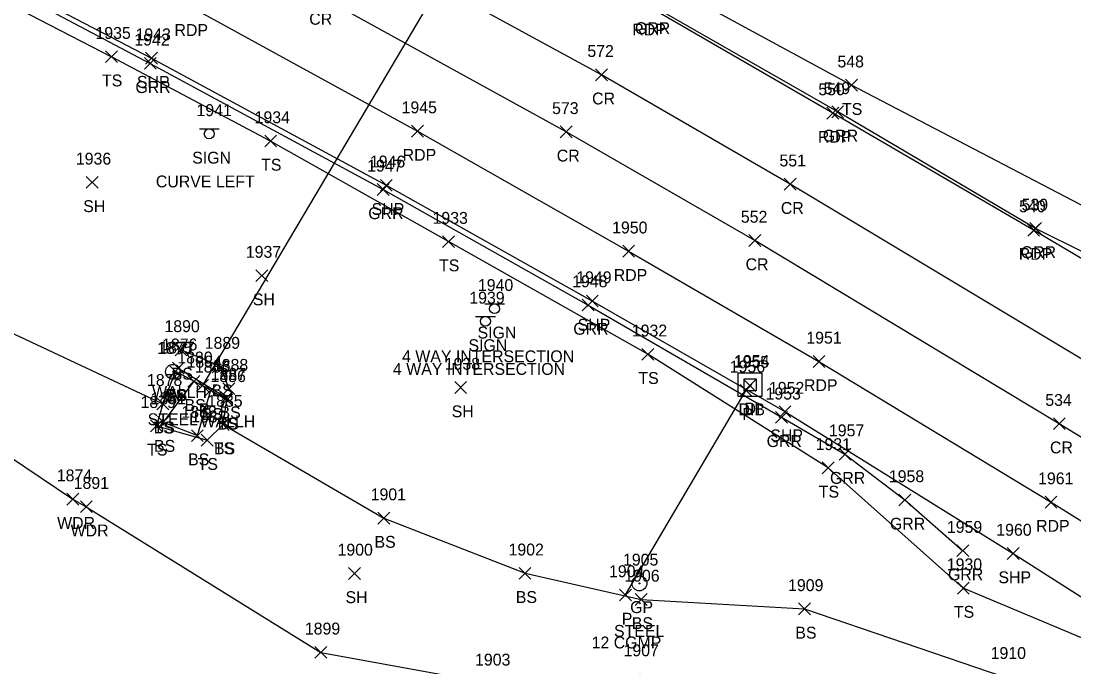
# Model space of a CAD drawing. Extents: x 1629176 to 1637209, y 606063 to 610167.
# Drawn here: x 1630435.7 to 1630613, y 606610.8 to 606719.6 of the extents above; entities that cross this region are included whole.
import ezdxf

# ---------------------------------------------------------------- set-up
doc = ezdxf.new("R2010")
doc.units = 0
for name, color, linetype in [('D_A', 7, 'Continuous'), ('D_C', 7, 'Continuous'), ('D_I', 7, 'Continuous'), ('D_TIC', 7, 'Continuous'), ('DCP', 7, 'Continuous'), ('DHW', 7, 'Continuous'), ('DS', 7, 'Continuous'), ('L_A', 7, 'Continuous'), ('L_I', 7, 'Continuous'), ('L_TIC', 7, 'Continuous'), ('LAWA', 7, 'Continuous'), ('LELB', 7, 'Continuous'), ('P_A', 7, 'Continuous'), ('P_I', 7, 'Continuous'), ('P_TIC', 7, 'Continuous'), ('PET', 7, 'Continuous'), ('PRC', 7, 'Continuous'), ('PSP', 7, 'Continuous'), ('R_A', 7, 'Continuous'), ('R_C', 7, 'Continuous'), ('R_I', 7, 'Continuous'), ('R_TIC', 7, 'Continuous'), ('RGP', 7, 'Continuous'), ('RGR', 7, 'Continuous'), ('S_A', 7, 'Continuous'), ('S_C', 7, 'Continuous'), ('S_I', 7, 'Continuous'), ('SSGN', 7, 'Continuous')]:
    doc.layers.add(name, color=color, linetype=linetype)

msp = doc.modelspace()

# ---------------------------------------------------------------- linework, layer by layer
at = {"layer": 'D_TIC'}
for points in [[(1630461.15, 606660.13), (1630463.15, 606662.13)], [(1630463.15, 606660.13), (1630461.15, 606662.13)], [(1630465.23, 606657.23), (1630467.23, 606659.23)], [(1630467.23, 606657.23), (1630465.23, 606659.23)], [(1630557.38, 606657.21), (1630559.38, 606659.21)], [(1630559.38, 606657.21), (1630557.38, 606659.21)], [(1630469.3, 606655.17), (1630471.3, 606657.17)], [(1630471.3, 606655.17), (1630469.3, 606657.17)], [(1630556.75, 606656.41), (1630558.75, 606658.41)], [(1630558.75, 606656.41), (1630556.75, 606658.41)], [(1630536.46, 606621.94), (1630538.46, 606623.94)], [(1630538.46, 606621.94), (1630536.46, 606623.94)]]:
    msp.add_lwpolyline(points, dxfattribs=at)
at = {"layer": 'DCP'}
for points in [[(1630562.44, 606820.77), (1630466.23, 606658.23)], [(1630537.46, 606622.94), (1630557.75, 606657.41)]]:
    msp.add_lwpolyline(points, dxfattribs=at)
at = {"layer": 'DHW'}
msp.add_lwpolyline([(1630462.15, 606661.13), (1630470.3, 606656.17)], dxfattribs=at)
at = {"layer": 'DS'}
for p, q in [((1630556.43, 606660.35), (1630560.43, 606660.35)), ((1630556.43, 606656.35), (1630556.43, 606660.35)), ((1630557.43, 606657.35), (1630557.43, 606659.35)), ((1630557.43, 606659.35), (1630559.43, 606659.35)), ((1630559.43, 606659.35), (1630559.43, 606657.35)), ((1630560.43, 606660.35), (1630560.43, 606656.35)), ((1630559.43, 606657.35), (1630557.43, 606657.35)), ((1630558.44, 606658.35), (1630558.44, 606658.35)), ((1630558.44, 606658.35), (1630558.44, 606658.35)), ((1630560.43, 606656.35), (1630556.43, 606656.35))]:
    msp.add_line(p, q, dxfattribs=at)
at = {"layer": 'L_TIC'}
for points in [[(1630449.89, 606712.6), (1630451.89, 606714.6)], [(1630451.89, 606712.6), (1630449.89, 606714.6)], [(1630449.89, 606712.6), (1630451.89, 606714.6)], [(1630451.89, 606712.6), (1630449.89, 606714.6)], [(1630574.5, 606707.79), (1630576.5, 606709.79)], [(1630576.5, 606707.79), (1630574.5, 606709.79)], [(1630476.7, 606698.4), (1630478.7, 606700.4)], [(1630478.7, 606698.4), (1630476.7, 606700.4)], [(1630446.65, 606691.43), (1630448.65, 606693.43)], [(1630448.65, 606691.43), (1630446.65, 606693.43)], [(1630506.65, 606681.45), (1630508.65, 606683.45)], [(1630508.65, 606681.45), (1630506.65, 606683.45)], [(1630475.21, 606675.73), (1630477.21, 606677.73)], [(1630477.21, 606675.73), (1630475.21, 606677.73)], [(1630461.6, 606663.21), (1630463.6, 606665.21)], [(1630463.6, 606663.21), (1630461.6, 606665.21)], [(1630540.22, 606662.48), (1630542.22, 606664.48)], [(1630542.22, 606662.48), (1630540.22, 606664.48)], [(1630460.65, 606659.61), (1630462.65, 606661.61)], [(1630462.65, 606659.61), (1630460.65, 606661.61)], [(1630460.65, 606659.61), (1630462.65, 606661.61)], [(1630462.65, 606659.61), (1630460.65, 606661.61)], [(1630468.3, 606660.4), (1630470.3, 606662.4)], [(1630470.3, 606660.4), (1630468.3, 606662.4)], [(1630463.76, 606657.93), (1630465.76, 606659.93)], [(1630465.76, 606657.93), (1630463.76, 606659.93)], [(1630463.76, 606657.93), (1630465.76, 606659.93)], [(1630465.76, 606657.93), (1630463.76, 606659.93)], [(1630466.64, 606656.41), (1630468.64, 606658.41)], [(1630468.64, 606656.41), (1630466.64, 606658.41)], [(1630466.64, 606656.41), (1630468.64, 606658.41)], [(1630468.64, 606656.41), (1630466.64, 606658.41)], [(1630469.66, 606656.69), (1630471.66, 606658.69)], [(1630471.66, 606656.69), (1630469.66, 606658.69)], [(1630508.7, 606656.87), (1630510.7, 606658.87)], [(1630510.7, 606656.87), (1630508.7, 606658.87)], [(1630458.56, 606654.15), (1630460.56, 606656.15)], [(1630460.56, 606654.15), (1630458.56, 606656.15)], [(1630458.56, 606654.15), (1630460.56, 606656.15)], [(1630460.56, 606654.15), (1630458.56, 606656.15)], [(1630469.33, 606654.8), (1630471.33, 606656.8)], [(1630471.33, 606654.8), (1630469.33, 606656.8)], [(1630469.33, 606654.8), (1630471.33, 606656.8)], [(1630471.33, 606654.8), (1630469.33, 606656.8)], [(1630457.49, 606650.43), (1630459.49, 606652.43)], [(1630459.49, 606650.43), (1630457.49, 606652.43)], [(1630458.62, 606651.05), (1630460.62, 606653.05)], [(1630460.62, 606651.05), (1630458.62, 606653.05)], [(1630468.72, 606650.64), (1630470.72, 606652.64)], [(1630470.72, 606650.64), (1630468.72, 606652.64)], [(1630468.72, 606650.64), (1630470.72, 606652.64)], [(1630470.72, 606650.64), (1630468.72, 606652.64)], [(1630464.36, 606648.78), (1630466.36, 606650.78)], [(1630466.36, 606648.78), (1630464.36, 606650.78)], [(1630466, 606648), (1630468, 606650)], [(1630468, 606648), (1630466, 606650)], [(1630570.59, 606643.34), (1630572.59, 606645.34)], [(1630572.59, 606643.34), (1630570.59, 606645.34)], [(1630443.38, 606638.08), (1630445.38, 606640.08)], [(1630445.38, 606638.08), (1630443.38, 606640.08)], [(1630445.66, 606636.81), (1630447.66, 606638.81)], [(1630447.66, 606636.81), (1630445.66, 606638.81)], [(1630495.75, 606634.89), (1630497.75, 606636.89)], [(1630497.75, 606634.89), (1630495.75, 606636.89)], [(1630490.82, 606625.57), (1630492.82, 606627.57)], [(1630492.82, 606625.57), (1630490.82, 606627.57)], [(1630519.54, 606625.59), (1630521.54, 606627.59)], [(1630521.54, 606625.59), (1630519.54, 606627.59)], [(1630593.34, 606623.1), (1630595.34, 606625.1)], [(1630595.34, 606623.1), (1630593.34, 606625.1)], [(1630539.08, 606621.19), (1630541.08, 606623.19)], [(1630541.08, 606621.19), (1630539.08, 606623.19)], [(1630566.61, 606619.59), (1630568.61, 606621.59)], [(1630568.61, 606619.59), (1630566.61, 606621.59)], [(1630485.16, 606612.28), (1630487.16, 606614.28)], [(1630487.16, 606612.28), (1630485.16, 606614.28)]]:
    msp.add_lwpolyline(points, dxfattribs=at)
at = {"layer": 'LAWA'}
msp.add_lwpolyline([(1630297.68, 606682.91), (1630335.71, 606675.48), (1630386.4, 606666.36), (1630422.65, 606653.68), (1630444.38, 606639.08), (1630446.66, 606637.81), (1630486.16, 606613.28), (1630514.89, 606608.05), (1630539.89, 606609.62), (1630562.09, 606603.08), (1630591.48, 606594.03), (1630626, 606578), (1630626.04, 606578.1), (1630670.33, 606553.73), (1630697.07, 606528.38), (1630722.88, 606501.58)], dxfattribs=at)
at = {"layer": 'LELB'}
for points in [[(1630772.3, 606583.26), (1630744.36, 606600.82), (1630702.09, 606628.01), (1630669.73, 606653.69), (1630639.16, 606677.6), (1630625.62, 606682.65), (1630575.5, 606708.79), (1630543.73, 606726.11), (1630517.88, 606742.14), (1630478.23, 606762.96), (1630430.43, 606788.65), (1630392.8, 606806.98), (1630357.66, 606823.31), (1630317.9, 606842.29), (1630273.51, 606862.27), (1630239.69, 606876.29), (1630209.67, 606888.82), (1630166.54, 606905.65), (1630125.1, 606921.22), (1630084.2, 606935.53), (1630049.16, 606947.36)], [(1630044.25, 606889.35), (1630091.41, 606872.59), (1630136.9, 606855.8), (1630181.87, 606838.43), (1630229.1, 606819.13), (1630265.76, 606803.15), (1630304.81, 606785.31), (1630348.18, 606765.13), (1630385.69, 606747.11), (1630426.71, 606726.12), (1630450.89, 606713.6)], [(1630053.59, 606794.16), (1630081.62, 606779.15), (1630106.52, 606768.08), (1630137.48, 606760.05), (1630167.15, 606751.57), (1630192.23, 606740.71), (1630218.23, 606736.11), (1630252.15, 606733.42), (1630290.4, 606729.57), (1630313.6, 606719.08), (1630348.91, 606706.34), (1630395.46, 606688.14), (1630428.07, 606669.89), (1630459.56, 606655.15)], [(1630743.82, 606536.58), (1630708.63, 606560.3), (1630674.18, 606582.22), (1630637.64, 606605.88), (1630594.34, 606624.1), (1630571.59, 606644.34), (1630541.22, 606663.48), (1630507.65, 606682.45), (1630477.7, 606699.4), (1630450.89, 606713.6)], [(1630470.66, 606657.69), (1630469.3, 606661.4), (1630462.6, 606664.21)], [(1630461.65, 606660.61), (1630459.56, 606655.15), (1630458.49, 606651.43), (1630467, 606649), (1630469.72, 606651.64), (1630470.33, 606655.8)], [(1630461.65, 606660.61), (1630464.76, 606658.93), (1630467.64, 606657.41), (1630470.33, 606655.8)], [(1630464.76, 606658.93), (1630459.62, 606652.05), (1630465.36, 606649.78), (1630467.64, 606657.41)], [(1630469.72, 606651.64), (1630496.75, 606635.89), (1630520.54, 606626.59), (1630540.08, 606622.19), (1630567.61, 606620.59), (1630601.15, 606609.16), (1630644.49, 606587.12), (1630679, 606566.75), (1630703.09, 606550.33), (1630739.27, 606526.44)]]:
    msp.add_lwpolyline(points, dxfattribs=at)
at = {"layer": 'P_TIC'}
for points in [[(1630456.64, 606712.36), (1630458.64, 606714.36)], [(1630458.64, 606712.36), (1630456.64, 606714.36)], [(1630532.4, 606709.56), (1630534.4, 606711.56)], [(1630534.4, 606709.56), (1630532.4, 606711.56)], [(1630571.37, 606703.1), (1630573.37, 606705.1)], [(1630573.37, 606703.1), (1630571.37, 606705.1)], [(1630501.44, 606700.07), (1630503.44, 606702.07)], [(1630503.44, 606700.07), (1630501.44, 606702.07)], [(1630526.45, 606699.94), (1630528.45, 606701.94)], [(1630528.45, 606699.94), (1630526.45, 606701.94)], [(1630496.17, 606690.94), (1630498.17, 606692.94)], [(1630498.17, 606690.94), (1630496.17, 606692.94)], [(1630564.18, 606691.12), (1630566.18, 606693.12)], [(1630566.18, 606691.12), (1630564.18, 606693.12)], [(1630605.18, 606683.39), (1630607.18, 606685.39)], [(1630607.18, 606683.39), (1630605.18, 606685.39)], [(1630558.24, 606681.64), (1630560.24, 606683.64)], [(1630560.24, 606681.64), (1630558.24, 606683.64)], [(1630536.98, 606679.83), (1630538.98, 606681.83)], [(1630538.98, 606679.83), (1630536.98, 606681.83)], [(1630530.87, 606671.45), (1630532.87, 606673.45)], [(1630532.87, 606671.45), (1630530.87, 606673.45)], [(1630569.03, 606661.27), (1630571.03, 606663.27)], [(1630571.03, 606661.27), (1630569.03, 606663.27)], [(1630563.31, 606652.82), (1630565.31, 606654.82)], [(1630565.31, 606652.82), (1630563.31, 606654.82)], [(1630609.5, 606650.79), (1630611.5, 606652.79)], [(1630611.5, 606650.79), (1630609.5, 606652.79)], [(1630608.11, 606637.58), (1630610.11, 606639.58)], [(1630610.11, 606637.58), (1630608.11, 606639.58)], [(1630601.72, 606628.92), (1630603.72, 606630.92)], [(1630603.72, 606628.92), (1630601.72, 606630.92)]]:
    msp.add_lwpolyline(points, dxfattribs=at)
at = {"layer": 'PET'}
for points in [[(1630769.62, 606580.83), (1630742.32, 606598.72), (1630700.55, 606625.63), (1630665.45, 606648.34), (1630621.98, 606674.98), (1630606.18, 606684.39), (1630572.37, 606704.1), (1630541.12, 606722.17), (1630498.96, 606745.43), (1630457.51, 606767.81), (1630420.78, 606786.67), (1630374.62, 606809.25), (1630335.12, 606827.65), (1630289.38, 606848.42), (1630250.13, 606865.31), (1630203.69, 606884.49), (1630159.86, 606901.83), (1630115.59, 606918.47), (1630070.26, 606934.37)], [(1630050.76, 606901.68), (1630096.23, 606885.67), (1630143.35, 606868.08), (1630186.15, 606851.44), (1630235.05, 606831.31), (1630271.1, 606815.81), (1630310.69, 606798.07), (1630353.79, 606777.93), (1630392.73, 606758.86), (1630432.29, 606738.62), (1630464.02, 606722.09), (1630502.44, 606701.07), (1630537.98, 606680.83), (1630570.03, 606662.27), (1630609.11, 606638.58), (1630644.7, 606616.38), (1630681.38, 606592.72), (1630715.14, 606570.86), (1630750.81, 606547.81)]]:
    msp.add_lwpolyline(points, dxfattribs=at)
at = {"layer": 'PRC'}
for points in [[(1630762, 606568.31), (1630732.48, 606587.66), (1630693.14, 606613.4), (1630657.5, 606636.16), (1630615.44, 606661.97), (1630565.18, 606692.12), (1630533.4, 606710.56), (1630491.42, 606733.47), (1630450.45, 606755.19), (1630412.78, 606774.87), (1630369.5, 606796.13), (1630328.6, 606815.23), (1630283.03, 606835.75), (1630244.34, 606852.21), (1630197.18, 606871.73), (1630154.28, 606888.46), (1630110.18, 606905.77), (1630065.36, 606921.68)], [(1630755.45, 606559.52), (1630726, 606578.65), (1630686.27, 606604.3), (1630651.63, 606626.53), (1630610.5, 606651.79), (1630559.24, 606682.64), (1630527.45, 606700.94), (1630485.76, 606723.98), (1630445.96, 606745.41), (1630407.11, 606765.59), (1630364.16, 606786.66), (1630323.37, 606805.55), (1630278.9, 606825.47), (1630240.3, 606842.26), (1630192.63, 606861.5), (1630149.2, 606878.91), (1630105.99, 606894.95), (1630061.18, 606910.94)]]:
    msp.add_lwpolyline(points, dxfattribs=at)
at = {"layer": 'PSP'}
msp.add_lwpolyline([(1630045.28, 606892.75), (1630092.08, 606875.64), (1630138.49, 606858.75), (1630183.19, 606841.37), (1630230, 606822.13), (1630266.88, 606805.89), (1630306.04, 606788.47), (1630348.79, 606768.34), (1630387.17, 606749.74), (1630427.91, 606728.87), (1630457.64, 606713.36), (1630497.17, 606691.94), (1630531.87, 606672.45), (1630564.31, 606653.82), (1630602.72, 606629.92), (1630638.6, 606607.1), (1630675.39, 606583.77), (1630709.63, 606561.3), (1630744.78, 606538.28)], dxfattribs=at)
at = {"layer": 'R_TIC'}
for points in [[(1630456.43, 606711.48), (1630458.43, 606713.48)], [(1630458.43, 606711.48), (1630456.43, 606713.48)], [(1630572.19, 606703.3), (1630574.19, 606705.3)], [(1630574.19, 606703.3), (1630572.19, 606705.3)], [(1630495.65, 606690.24), (1630497.65, 606692.24)], [(1630497.65, 606690.24), (1630495.65, 606692.24)], [(1630605.52, 606683.67), (1630607.52, 606685.67)], [(1630607.52, 606683.67), (1630605.52, 606685.67)], [(1630530.18, 606670.77), (1630532.18, 606672.77)], [(1630532.18, 606670.77), (1630530.18, 606672.77)], [(1630562.73, 606651.86), (1630564.73, 606653.86)], [(1630564.73, 606651.86), (1630562.73, 606653.86)], [(1630573.41, 606645.66), (1630575.41, 606647.66)], [(1630575.41, 606645.66), (1630573.41, 606647.66)], [(1630583.49, 606637.94), (1630585.49, 606639.94)], [(1630585.49, 606637.94), (1630583.49, 606639.94)], [(1630593.27, 606629.4), (1630595.27, 606631.4)], [(1630595.27, 606629.4), (1630593.27, 606631.4)]]:
    msp.add_lwpolyline(points, dxfattribs=at)
at = {"layer": 'RGP'}
for p, q in [((1630461.27, 606660.53), (1630461.27, 606660.53)), ((1630539.8, 606624.89), (1630539.8, 606624.89))]:
    msp.add_line(p, q, dxfattribs=at)
for centre, radius in [((1630461.27, 606660.53), 1.25), ((1630461.27, 606660.53), 0.0833), ((1630539.8, 606624.89), 1.25), ((1630539.8, 606624.89), 0.0833)]:
    msp.add_circle(centre, radius, dxfattribs=at)
at = {"layer": 'RGR'}
for points in [[(1630636.53, 606670.83), (1630623.24, 606676.36), (1630606.52, 606684.67), (1630573.19, 606704.3), (1630541.55, 606722.4), (1630499.19, 606745.82), (1630457.55, 606768.16), (1630421.01, 606787.01), (1630374.76, 606809.6), (1630335.39, 606828.12), (1630289.48, 606848.85), (1630250.07, 606865.82), (1630203.7, 606885.03), (1630160.01, 606902.28), (1630115.67, 606918.76), (1630070.66, 606934.74)], [(1630044.87, 606891.43), (1630091.95, 606875), (1630137.84, 606857.9), (1630182.67, 606840.57), (1630230.01, 606820.88), (1630266.36, 606805.24), (1630305.77, 606787.45), (1630348.91, 606767.39), (1630386.68, 606748.91), (1630427.72, 606728.18), (1630457.43, 606712.48), (1630496.65, 606691.24), (1630531.18, 606671.77), (1630563.73, 606652.86), (1630574.41, 606646.66), (1630584.49, 606638.94), (1630594.27, 606630.4)]]:
    msp.add_lwpolyline(points, dxfattribs=at)
at = {"layer": 'SSGN'}
for p, q in [((1630465.71, 606701.44), (1630469.04, 606701.44)), ((1630467.36, 606700.61), (1630467.36, 606700.61)), ((1630513.75, 606671.99), (1630517.09, 606671.99)), ((1630512.22, 606669.86), (1630515.56, 606669.86)), ((1630515.4, 606671.16), (1630515.4, 606671.16)), ((1630513.87, 606669.03), (1630513.87, 606669.03))]:
    msp.add_line(p, q, dxfattribs=at)
for centre in [(1630467.36, 606700.61), (1630515.4, 606671.16), (1630513.87, 606669.03)]:
    msp.add_circle(centre, 0.833, dxfattribs=at)

# ---------------------------------------------------------------- texts
at = {"layer": 'D_A'}
for s, p in [('WALLH', (1630457.74, 606656.13)), ('P', (1630465.61, 606653.23)), ('DIB', (1630556.48, 606653.21)), ('P', (1630557.13, 606652.41)), ('DI', (1630557.49, 606653.35)), ('WALLH', (1630465.89, 606651.17)), ('P', (1630536.83, 606617.94))]:
    msp.add_text(s, height=2, dxfattribs=at).set_placement(p)
at = {"layer": 'D_C'}
msp.add_text('12 CGMP', height=2, dxfattribs=at).set_placement((1630531.75, 606613.94))
at = {"layer": 'D_I'}
for s, p in [('1876', (1630459.41, 606664.13)), ('1884', (1630463.54, 606661.23)), ('1955', (1630555.68, 606661.21)), ('1954', (1630555.75, 606661.35)), ('1887', (1630467.61, 606659.17)), ('1956', (1630555.01, 606660.41)), ('1904', (1630534.68, 606625.94))]:
    msp.add_text(s, height=2, dxfattribs=at).set_placement(p)
at = {"layer": 'L_A'}
for s, p in [('TS', (1630449.3, 606708.6)), ('TS', (1630449.3, 606708.6)), ('TS', (1630573.91, 606703.79)), ('TS', (1630476.1, 606694.4)), ('SH', (1630446.14, 606687.43)), ('TS', (1630506.06, 606677.45)), ('SH', (1630474.7, 606671.73)), ('BS', (1630461.04, 606659.21)), ('TS', (1630539.63, 606658.48)), ('TS', (1630460.06, 606655.61)), ('BS', (1630460.09, 606655.61)), ('BS', (1630467.75, 606656.4)), ('BS', (1630463.2, 606653.93)), ('BS', (1630463.2, 606653.93)), ('BS', (1630466.08, 606652.41)), ('BS', (1630466.08, 606652.41)), ('BS', (1630469.1, 606652.69)), ('SH', (1630508.19, 606652.87)), ('TS', (1630457.97, 606650.15)), ('BS', (1630458, 606650.15)), ('TS', (1630468.74, 606650.8)), ('BS', (1630468.77, 606650.8)), ('TS', (1630456.9, 606646.43)), ('BS', (1630458.06, 606647.05)), ('TS', (1630468.13, 606646.64)), ('BS', (1630468.16, 606646.64)), ('BS', (1630463.8, 606644.78)), ('TS', (1630465.41, 606644)), ('TS', (1630570, 606639.34)), ('WDR', (1630441.74, 606634.08)), ('WDR', (1630444.02, 606632.81)), ('BS', (1630495.19, 606630.89)), ('SH', (1630490.31, 606621.57)), ('BS', (1630518.98, 606621.59)), ('TS', (1630592.75, 606619.1)), ('BS', (1630538.52, 606617.19)), ('BS', (1630566.05, 606615.59))]:
    msp.add_text(s, height=2, dxfattribs=at).set_placement(p)
at = {"layer": 'L_I'}
for s, p in [('1935', (1630448.2, 606716.6)), ('1935', (1630448.2, 606716.6)), ('548', (1630573.14, 606711.79)), ('1934', (1630475, 606702.4)), ('1936', (1630444.9, 606695.43)), ('1933', (1630504.96, 606685.45)), ('1937', (1630473.52, 606679.73)), ('1890', (1630459.82, 606667.21)), ('1932', (1630538.52, 606666.48)), ('1889', (1630466.6, 606664.4)), ('1877', (1630458.95, 606663.61)), ('1877', (1630458.95, 606663.61)), ('1880', (1630461.98, 606661.93)), ('1880', (1630461.98, 606661.93)), ('1888', (1630467.97, 606660.69)), ('1938', (1630507.01, 606660.87)), ('1883', (1630464.94, 606660.41)), ('1883', (1630464.94, 606660.41)), ('1886', (1630467.58, 606658.8)), ('1886', (1630467.58, 606658.8)), ('1878', (1630456.87, 606658.15)), ('1878', (1630456.87, 606658.15)), ('1879', (1630455.79, 606654.43)), ('1881', (1630457.49, 606655.05)), ('1885', (1630467.03, 606654.64)), ('1885', (1630467.03, 606654.64)), ('1882', (1630462.67, 606652.78)), ('1382', (1630464.31, 606652)), ('1931', (1630569.47, 606647.34)), ('1874', (1630441.69, 606642.08)), ('1891', (1630444.53, 606640.81)), ('1901', (1630494.54, 606638.89)), ('1900', (1630488.96, 606629.57)), ('1902', (1630517.76, 606629.59)), ('1930', (1630591.56, 606627.1)), ('1906', (1630537.25, 606625.19)), ('1909', (1630564.83, 606623.59)), ('1899', (1630483.46, 606616.28)), ('1907', (1630537.12, 606612.62)), ('1903', (1630512.12, 606611.05)), ('1903', (1630512.12, 606611.05)), ('1910', (1630598.94, 606612.16))]:
    msp.add_text(s, height=2, dxfattribs=at).set_placement(p)
at = {"layer": 'P_A'}
for s, p in [('CR', (1630484.2, 606718.98)), ('RDP', (1630461.51, 606717.09)), ('RDP', (1630538.61, 606717.17)), ('SHP', (1630455.18, 606708.36)), ('CR', (1630531.83, 606705.56)), ('RDP', (1630569.85, 606699.1)), ('RDP', (1630499.93, 606696.07)), ('CR', (1630525.88, 606695.94)), ('CR', (1630563.61, 606687.12)), ('SHP', (1630494.7, 606686.94)), ('RDP', (1630603.67, 606679.39)), ('CR', (1630557.67, 606677.64)), ('RDP', (1630535.47, 606675.83)), ('SHP', (1630529.4, 606667.45)), ('RDP', (1630567.51, 606657.27)), ('SHP', (1630561.84, 606648.82)), ('CR', (1630608.93, 606646.79)), ('RDP', (1630606.59, 606633.58)), ('SHP', (1630600.25, 606624.92))]:
    msp.add_text(s, height=2, dxfattribs=at).set_placement(p)
at = {"layer": 'P_I'}
for s, p in [('1943', (1630454.95, 606716.36)), ('572', (1630531.03, 606713.56)), ('550', (1630569.92, 606707.1)), ('1945', (1630499.75, 606704.07)), ('573', (1630525.09, 606703.94)), ('1946', (1630494.42, 606694.94)), ('551', (1630563.38, 606695.12)), ('540', (1630603.73, 606687.39)), ('552', (1630556.88, 606685.64)), ('1950', (1630535.2, 606683.83)), ('1949', (1630529.16, 606675.45)), ('1951', (1630567.9, 606665.27)), ('1952', (1630561.61, 606656.82)), ('534', (1630608.14, 606654.79)), ('1961', (1630606.93, 606641.58)), ('1960', (1630599.89, 606632.92))]:
    msp.add_text(s, height=2, dxfattribs=at).set_placement(p)
at = {"layer": 'R_A'}
for s, p in [('GRR', (1630539.04, 606717.4)), ('GRR', (1630454.92, 606707.48)), ('GRR', (1630570.68, 606699.3)), ('GRR', (1630494.14, 606686.24)), ('GRR', (1630604.01, 606679.67)), ('GRR', (1630528.66, 606666.77)), ('GP', (1630459.71, 606655.53)), ('GRR', (1630561.22, 606647.86)), ('GRR', (1630571.89, 606641.66)), ('GRR', (1630581.98, 606633.94)), ('GRR', (1630591.76, 606625.4)), ('GP', (1630538.24, 606619.89))]:
    msp.add_text(s, height=2, dxfattribs=at).set_placement(p)
at = {"layer": 'R_C'}
for p in [(1630456.99, 606651.53), (1630535.52, 606615.89)]:
    msp.add_text('STEEL', height=2, dxfattribs=at).set_placement(p)
at = {"layer": 'R_I'}
for s, p in [('1942', (1630454.74, 606715.48)), ('549', (1630570.82, 606707.3)), ('1947', (1630493.95, 606694.24)), ('539', (1630604.15, 606687.67)), ('1948', (1630528.48, 606674.77)), ('1875', (1630458.58, 606663.53)), ('1953', (1630561.04, 606655.86)), ('1957', (1630571.71, 606649.66)), ('1958', (1630581.8, 606641.94)), ('1959', (1630591.57, 606633.4)), ('1905', (1630537.03, 606627.89))]:
    msp.add_text(s, height=2, dxfattribs=at).set_placement(p)
at = {"layer": 'S_A'}
for p in [(1630464.49, 606695.59), (1630512.54, 606666.14), (1630511.01, 606664.01)]:
    msp.add_text('SIGN', height=2, dxfattribs=at).set_placement(p)
at = {"layer": 'S_C'}
for s, p in [('CURVE LEFT', (1630458.37, 606691.59)), ('4 WAY INTERSECTION', (1630499.83, 606662.14)), ('4 WAY INTERSECTION', (1630498.3, 606660.01))]:
    msp.add_text(s, height=2, dxfattribs=at).set_placement(p)
at = {"layer": 'S_I'}
for s, p in [('1941', (1630465.21, 606703.59)), ('1940', (1630512.6, 606674.14)), ('1939', (1630511.15, 606672.01))]:
    msp.add_text(s, height=2, dxfattribs=at).set_placement(p)

doc.saveas('drawing.dxf')
